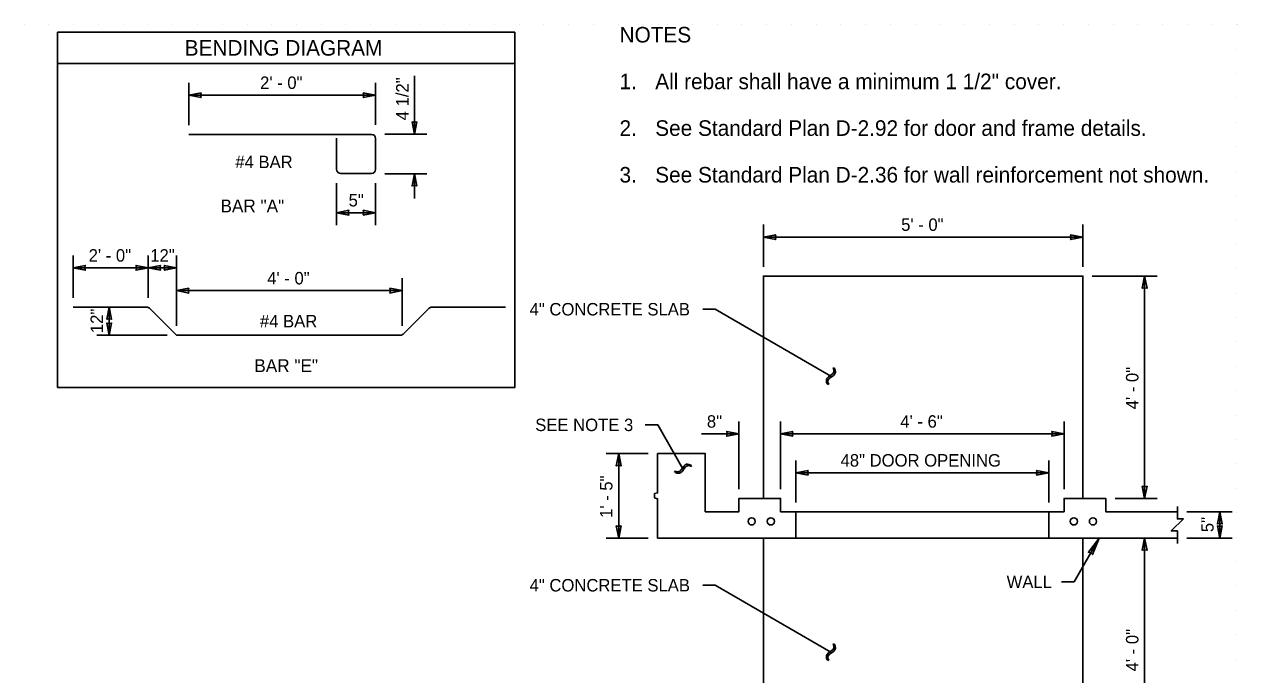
# Model space of a CAD drawing. Extents: x 99862 to 103151, y 100000 to 102076.
# Drawn here: x 101591 to 103151, y 101240 to 102076 of the extents above; entities that cross this region are included whole.
import ezdxf

# ---------------------------------------------------------------- set-up
doc = ezdxf.new("R2010")
doc.units = 0
for name, color, linetype in [('Level 1', 7, 'Continuous'), ('Level 13', 7, 'Continuous'), ('Level 15', 7, 'Continuous'), ('Level 16', 7, 'Continuous'), ('Level 17', 7, 'Continuous'), ('Level 19', 7, 'Continuous'), ('Level 20', 7, 'Continuous'), ('Level 60', 7, 'Continuous')]:
    doc.layers.add(name, color=color, linetype=linetype)

msp = doc.modelspace()

# ---------------------------------------------------------------- linework, layer by layer
at = {"layer": 'Level 1'}
for p, q in [((101590.9, 102075), (101590.9, 102075)), ((101622.7, 102075), (101622.7, 102075)), ((101654.5, 102075), (101654.5, 102075)), ((101686.4, 102075), (101686.4, 102075)), ((101718.2, 102075), (101718.2, 102075)), ((101750, 102075), (101750, 102075)), ((101781.8, 102075), (101781.8, 102075)), ((101813.6, 102075), (101813.6, 102075)), ((101845.5, 102075), (101845.5, 102075)), ((101877.3, 102075), (101877.3, 102075)), ((101909.1, 102075), (101909.1, 102075)), ((101940.9, 102075), (101940.9, 102075)), ((101972.7, 102075), (101972.7, 102075)), ((102004.5, 102075), (102004.5, 102075)), ((102036.4, 102075), (102036.4, 102075)), ((102068.2, 102075), (102068.2, 102075)), ((102100, 102075), (102100, 102075)), ((102131.8, 102075), (102131.8, 102075)), ((102163.6, 102075), (102163.6, 102075)), ((102195.5, 102075), (102195.5, 102075)), ((102227.3, 102075), (102227.3, 102075)), ((102259.1, 102075), (102259.1, 102075)), ((102290.9, 102075), (102290.9, 102075)), ((102322.7, 102075), (102322.7, 102075)), ((102354.5, 102075), (102354.5, 102075)), ((102386.4, 102075), (102386.4, 102075)), ((102418.2, 102075), (102418.2, 102075)), ((102450, 102075), (102450, 102075)), ((102481.8, 102075), (102481.8, 102075)), ((102513.6, 102075), (102513.6, 102075)), ((102545.5, 102075), (102545.5, 102075)), ((102577.3, 102075), (102577.3, 102075)), ((102609.1, 102075), (102609.1, 102075)), ((102640.9, 102075), (102640.9, 102075)), ((102672.7, 102075), (102672.7, 102075)), ((102704.5, 102075), (102704.5, 102075)), ((102736.4, 102075), (102736.4, 102075)), ((102768.2, 102075), (102768.2, 102075)), ((102800, 102075), (102800, 102075)), ((102831.8, 102075), (102831.8, 102075)), ((102863.6, 102075), (102863.6, 102075)), ((102895.5, 102075), (102895.5, 102075)), ((102927.3, 102075), (102927.3, 102075)), ((102959.1, 102075), (102959.1, 102075)), ((102990.9, 102075), (102990.9, 102075)), ((103022.7, 102075), (103022.7, 102075)), ((103054.5, 102075), (103054.5, 102075)), ((103086.4, 102075), (103086.4, 102075)), ((103118.2, 102075), (103118.2, 102075)), ((103150, 102075), (103150, 102075)), ((103150, 102043.6), (103150, 102043.6)), ((103150, 102012.3), (103150, 102012.3)), ((103150, 101980.9), (103150, 101980.9)), ((103150, 101949.6), (103150, 101949.6)), ((103150, 101918.2), (103150, 101918.2)), ((103150, 101886.9), (103150, 101886.9)), ((103150, 101855.5), (103150, 101855.5)), ((103150, 101824.2), (103150, 101824.2)), ((103150, 101792.8), (103150, 101792.8)), ((103150, 101761.4), (103150, 101761.4)), ((103150, 101730.1), (103150, 101730.1)), ((103150, 101698.7), (103150, 101698.7)), ((103150, 101667.4), (103150, 101667.4)), ((103150, 101636), (103150, 101636)), ((103150, 101604.7), (103150, 101604.7)), ((103150, 101573.3), (103150, 101573.3)), ((103150, 101541.9), (103150, 101541.9)), ((103150, 101510.6), (103150, 101510.6)), ((103150, 101479.2), (103150, 101479.2)), ((103150, 101447.9), (103150, 101447.9)), ((103150, 101416.5), (103150, 101416.5)), ((103150, 101385.2), (103150, 101385.2)), ((103150, 101353.8), (103150, 101353.8)), ((103150, 101322.5), (103150, 101322.5)), ((103150, 101291.1), (103150, 101291.1)), ((103150, 101259.7), (103150, 101259.7))]:
    msp.add_line(p, q, dxfattribs=at)
at = {"layer": 'Level 13'}
for p, q in [((101802.5, 101933.9), (102037.5, 101933.9)), ((101992.5, 101888.9), (101992.5, 101929.1)), ((102042.5, 101928.9), (102042.5, 101888.9)), ((102037.5, 101883.9), (101997.5, 101883.9))]:
    msp.add_line(p, q, dxfattribs=at)
for points in [[(101653.7, 101712.1), (101748.3, 101712.1)], [(101751.8, 101710.6), (101785.2, 101677.3)], [(102078.1, 101677.3), (102111.5, 101710.6)], [(102115, 101712.1), (102209.6, 101712.1)], [(101788.7, 101675.8), (102074.6, 101675.8)]]:
    msp.add_lwpolyline(points, dxfattribs=at)
for centre in [(102526.1, 101436.7), (102550.7, 101436.7), (102940.3, 101436.7), (102964.9, 101436.7)]:
    msp.add_circle(centre, 4.63, dxfattribs=at)
for centre, start, end in [((102037.5, 101928.9), 0, 90), ((101997.5, 101888.9), 180, 270), ((102037.5, 101888.9), 270, 0), ((101748.3, 101707.1), 45, 90), ((102115, 101707.1), 90, 135), ((101788.7, 101680.8), 225, 270), ((102074.6, 101680.8), 270, 315)]:
    msp.add_arc(centre, 5, start, end, dxfattribs=at)
at = {"layer": 'Level 15'}
for p, q in [((101802.5, 102000.4), (101802.5, 101945.9)), ((102042.5, 102000.4), (102042.5, 101946.3)), ((102092.5, 102009.2), (102092.5, 101934.3)), ((102042.5, 101984.4), (101802.5, 101984.4)), ((102108.5, 101934.3), (102054.5, 101934.3)), ((102108.5, 101883.4), (102054.5, 101883.4)), ((102092.5, 101883.4), (102092.5, 101851.4)), ((101992.5, 101871.4), (101992.5, 101817.4)), ((102042.5, 101871.4), (102042.5, 101817.4)), ((102042.5, 101833.4), (101992.5, 101833.4)), ((102541.3, 101764), (102541.3, 101818)), ((102951.9, 101764), (102951.9, 101818)), ((102951.9, 101802), (102541.3, 101802)), ((101653.7, 101778.5), (101653.7, 101724.1)), ((101750.4, 101778.5), (101750.4, 101724.1)), ((101786.6, 101778.5), (101786.6, 101687.8)), ((101750.4, 101762.5), (101653.7, 101762.5)), ((101786.6, 101762.5), (101750.4, 101762.5)), ((103047.3, 101752), (102963.9, 101752)), ((103031.3, 101466.1), (103031.3, 101752)), ((102076.7, 101749.2), (102076.7, 101687.8)), ((102076.7, 101733.2), (101786.6, 101733.2)), ((101700.1, 101712.1), (101700.1, 101675.8)), ((102463.2, 101709.3), (102479.2, 101709.3)), ((102628, 101623.4), (102479.2, 101709.3)), ((101774.6, 101675.8), (101684.1, 101675.8)), ((102509.7, 101478.1), (102509.7, 101565.1)), ((102563.3, 101478.1), (102563.3, 101565.1)), ((102927.7, 101478.1), (102927.7, 101565.1)), ((102389.3, 101560.7), (102405.3, 101560.7)), ((102437.8, 101504.4), (102405.3, 101560.7)), ((102461.5, 101549.1), (102509.7, 101549.1)), ((102927.7, 101549.1), (102563.3, 101549.1)), ((102339.1, 101523.7), (102393.1, 101523.7)), ((102355.1, 101415.2), (102355.1, 101523.7)), ((102583, 101461.1), (102583, 101515.1)), ((102908, 101461.1), (102908, 101515.1)), ((102908, 101499.1), (102583, 101499.1)), ((103047.3, 101466.1), (102993.3, 101466.1)), ((103085.4, 101449.1), (103144, 101449.1)), ((103128, 101415.2), (103128, 101449.1)), ((102339.1, 101415.2), (102393.1, 101415.2)), ((102973, 101415.2), (102940.5, 101358.9)), ((103031.3, 101415.2), (103031.3, 101129.3)), ((103085.4, 101415.2), (103144, 101415.2)), ((102463.2, 101354.6), (102479.2, 101354.6)), ((102628, 101268.7), (102479.2, 101354.6)), ((102924.5, 101358.9), (102940.5, 101358.9))]:
    msp.add_line(p, q, dxfattribs=at)
for points in [[(101802.5, 101984.4), (101818.2, 101981.3), (101817.5, 101984.4), (101818.2, 101987.4)], [(102042.5, 101984.4), (102026.8, 101987.4), (102027.5, 101984.4), (102026.8, 101981.3)], [(102092.5, 101934.3), (102095.6, 101950.1), (102092.5, 101949.3), (102089.4, 101950.1)], [(102092.5, 101883.4), (102089.4, 101867.7), (102092.5, 101868.4), (102095.6, 101867.7)], [(101992.5, 101833.4), (102008.2, 101830.3), (102007.5, 101833.4), (102008.2, 101836.5)], [(102042.5, 101833.4), (102026.8, 101836.5), (102027.5, 101833.4), (102026.8, 101830.3)], [(102541.3, 101802), (102557.1, 101805.1), (102556.3, 101802), (102557.1, 101798.9)], [(102951.9, 101802), (102936.2, 101798.9), (102936.9, 101802), (102936.2, 101805.1)], [(101653.7, 101762.5), (101669.4, 101759.4), (101668.7, 101762.5), (101669.4, 101765.6)], [(101750.4, 101762.5), (101734.6, 101765.6), (101735.4, 101762.5), (101734.6, 101759.4)], [(101750.4, 101762.5), (101766.1, 101759.4), (101765.4, 101762.5), (101766.1, 101765.6)], [(101786.6, 101762.5), (101770.9, 101765.6), (101771.6, 101762.5), (101770.9, 101759.4)], [(103031.3, 101752), (103034.4, 101736.3), (103031.3, 101737), (103028.2, 101736.3)], [(101786.6, 101733.2), (101802.3, 101730.1), (101801.6, 101733.2), (101802.3, 101736.2)], [(102076.7, 101733.2), (102060.9, 101736.2), (102061.7, 101733.2), (102060.9, 101730.1)], [(101700.1, 101712.1), (101697.1, 101696.4), (101700.1, 101697.1), (101703.2, 101696.4)], [(101700.1, 101675.8), (101703.2, 101691.6), (101700.1, 101690.8), (101697.1, 101691.6)], [(102509.7, 101549.1), (102494, 101552.2), (102494.7, 101549.1), (102494, 101546.1)], [(102563.3, 101549.1), (102579, 101552.2), (102578.3, 101549.1), (102579, 101546.1)], [(102927.7, 101549.1), (102912, 101546.1), (102912.7, 101549.1), (102912, 101552.2)], [(102355.1, 101523.7), (102352, 101507.9), (102355.1, 101508.7), (102358.2, 101507.9)], [(102583, 101499.1), (102598.7, 101502.2), (102598, 101499.1), (102598.7, 101496.1)], [(102908, 101499.1), (102892.3, 101496.1), (102893, 101499.1), (102892.3, 101502.2)], [(103031.3, 101466.1), (103028.2, 101481.8), (103031.3, 101481.1), (103034.4, 101481.8)], [(103128, 101449.1), (103124.9, 101433.4), (103128, 101434.1), (103131.1, 101433.4)], [(102355.1, 101415.2), (102352, 101430.9), (102355.1, 101430.2), (102358.2, 101430.9)], [(103128, 101415.2), (103124.9, 101430.9), (103128, 101430.2), (103131.1, 101430.9)], [(102973, 101415.2), (102964.2, 101393.9), (102962.1, 101396.3), (102959, 101396.9)], [(103031.3, 101415.2), (103028.2, 101399.5), (103031.3, 101400.2), (103034.4, 101399.5)]]:
    msp.add_lwpolyline(points, close=True, dxfattribs=at)
msp.add_lwpolyline([(103073.4, 101455.9), (103073.4, 101439.9), (103081.1, 101439.9), (103065.6, 101424.4), (103073.4, 101424.4), (103073.4, 101408.4)], dxfattribs=at)
at = {"layer": 'Level 16'}
for points in [[(102466.4, 101449.1), (102509.7, 101449.1), (102509.7, 101466.1), (102563.3, 101466.1), (102563.3, 101449.1), (102583, 101449.1), (102583, 101415.2), (102405.1, 101415.2), (102405.1, 101465.8), (102401.2, 101466.8), (102401.2, 101472.4), (102405.1, 101473.3), (102405.1, 101523.7), (102466.4, 101523.7)], [(102981.3, 101449.1), (103073.4, 101449.1), (103073.4, 101439.9), (103081.1, 101439.9), (103065.6, 101424.4), (103073.4, 101424.4), (103073.4, 101415.2), (102908, 101415.2), (102908, 101449.1), (102927.7, 101449.1), (102927.7, 101466.1), (102981.3, 101466.1)]]:
    msp.add_lwpolyline(points, close=True, dxfattribs=at)
at = {"layer": 'Level 17'}
for points in [[(102541.3, 101466.1), (102541.3, 101752), (102951.9, 101752), (102951.9, 101466.1)], [(102405.1, 101415.2), (102405.1, 101465.8), (102401.2, 101466.8), (102401.2, 101472.4), (102405.1, 101473.3), (102405.1, 101523.7), (102466.4, 101523.7), (102466.4, 101449.1), (102509.7, 101449.1), (102509.7, 101466.1), (102563.3, 101466.1), (102563.3, 101449.1), (102583, 101449.1), (102583, 101415.2), (102405.1, 101415.2)], [(103073.4, 101449.1), (102981.3, 101449.1), (102981.3, 101466.1), (102927.7, 101466.1), (102927.7, 101449.1), (102908, 101449.1), (102908, 101415.2), (103073.4, 101415.2)], [(102583, 101449.1), (102908, 101449.1)], [(102541.3, 101415.2), (102541.3, 101129.3), (102951.9, 101129.3), (102951.9, 101415.2)], [(102583, 101415.2), (102908, 101415.2)]]:
    msp.add_lwpolyline(points, dxfattribs=at)
at = {"layer": 'Level 19'}
for points in [[(102221.7, 102065.3), (101633.8, 102065.3), (101633.8, 102025.1), (102221.7, 102025.1)], [(102221.7, 102025.1), (101633.8, 102025.1), (101633.8, 101608.9), (102221.7, 101608.9)]]:
    msp.add_lwpolyline(points, close=True, dxfattribs=at)
at = {"layer": 'Level 20'}
for p, q in [((102624.8, 101622.6), (102628.5, 101625.1)), ((102628.5, 101625.1), (102630.4, 101626.5)), ((102630.4, 101626.5), (102631.4, 101627.6)), ((102631.9, 101630.6), (102631, 101634.2)), ((102631, 101634.2), (102632.8, 101633.2)), ((102631.4, 101627.6), (102631.9, 101629)), ((102633, 101626.2), (102631.5, 101624.3)), ((102631.9, 101629), (102631.9, 101630.6)), ((102632.8, 101633.2), (102633.6, 101631.1)), ((102633.7, 101627.8), (102633, 101626.2)), ((102633.6, 101631.1), (102633.8, 101629.4)), ((102633.8, 101629.4), (102633.7, 101627.8)), ((102622.2, 101617.2), (102622.4, 101618.9)), ((102622.5, 101615.4), (102622.2, 101617.2)), ((102622.4, 101618.9), (102623.1, 101620.5)), ((102623.3, 101613.6), (102622.5, 101615.4)), ((102623.1, 101620.5), (102624.8, 101622.6)), ((102625.1, 101612.5), (102623.3, 101613.6)), ((102624.2, 101617.9), (102624.1, 101616.5)), ((102624.1, 101616.5), (102624.4, 101614.8)), ((102624.7, 101619.1), (102624.2, 101617.9)), ((102624.4, 101614.8), (102625.1, 101612.5)), ((102626, 101620.6), (102624.7, 101619.1)), ((102628.1, 101622.1), (102626, 101620.6)), ((102631.5, 101624.3), (102628.1, 101622.1)), ((102429.3, 101500.7), (102427, 101501.4)), ((102427, 101501.4), (102428, 101499.6)), ((102428, 101499.6), (102429.8, 101498.8)), ((102431, 101500.4), (102429.3, 101500.7)), ((102432.3, 101500.6), (102431, 101500.4)), ((102433.6, 101501.1), (102432.3, 101500.6)), ((102435, 101502.3), (102433.6, 101501.1)), ((102434.9, 101499.4), (102437, 101501.2)), ((102436.5, 101504.4), (102435, 101502.3)), ((102438.8, 101507.8), (102436.5, 101504.4)), ((102437, 101501.2), (102439.5, 101504.8)), ((102440.7, 101509.4), (102438.8, 101507.8)), ((102439.5, 101504.8), (102440.9, 101506.8)), ((102442.2, 101510), (102440.7, 101509.4)), ((102440.9, 101506.8), (102442.1, 101507.7)), ((102442.1, 101507.7), (102443.4, 101508.2)), ((102443.8, 101510.2), (102442.2, 101510)), ((102443.4, 101508.2), (102445.1, 101508.3)), ((102445.6, 101509.9), (102443.8, 101510.2)), ((102445.1, 101508.3), (102448.6, 101507.3)), ((102447.6, 101509.2), (102445.6, 101509.9)), ((102448.6, 101507.3), (102447.6, 101509.2)), ((102429.8, 101498.8), (102431.6, 101498.6)), ((102431.6, 101498.6), (102433.3, 101498.8)), ((102433.3, 101498.8), (102434.9, 101499.4)), ((102622.4, 101264.2), (102623.1, 101265.8)), ((102623.1, 101265.8), (102624.8, 101267.9)), ((102626, 101265.9), (102624.7, 101264.4)), ((102624.8, 101267.9), (102628.5, 101270.4)), ((102628.1, 101267.3), (102626, 101265.9)), ((102631.5, 101269.6), (102628.1, 101267.3)), ((102628.5, 101270.4), (102630.4, 101271.8)), ((102630.4, 101271.8), (102631.4, 101272.9)), ((102631.9, 101275.9), (102631, 101279.5)), ((102631, 101279.5), (102632.8, 101278.4)), ((102631.4, 101272.9), (102631.9, 101274.3)), ((102633, 101271.5), (102631.5, 101269.6)), ((102631.9, 101274.3), (102631.9, 101275.9)), ((102632.8, 101278.4), (102633.6, 101276.4)), ((102633.7, 101273.1), (102633, 101271.5)), ((102633.6, 101276.4), (102633.8, 101274.7)), ((102633.8, 101274.7), (102633.7, 101273.1)), ((102622.2, 101262.5), (102622.4, 101264.2)), ((102622.5, 101260.7), (102622.2, 101262.5)), ((102623.3, 101258.9), (102622.5, 101260.7)), ((102625.1, 101257.8), (102623.3, 101258.9)), ((102624.2, 101263.2), (102624.1, 101261.8)), ((102624.1, 101261.8), (102624.4, 101260.1)), ((102624.7, 101264.4), (102624.2, 101263.2)), ((102624.4, 101260.1), (102625.1, 101257.8))]:
    msp.add_line(p, q, dxfattribs=at)
at = {"layer": 'Level 60'}
msp.add_line((103151, 102075.5), (103151, 102075.5), dxfattribs=at)

# ---------------------------------------------------------------- texts
at = {"layer": 'Level 19'}
msp.add_text('BENDING DIAGRAM', height=20, dxfattribs=at).set_placement((101797.2, 102035.2))
at = {"layer": 'Level 20'}
for s, height, p in [('NOTES', 20, (102356.2, 102052.1)), ('2\' - 0"', 16, (101894.1, 101992.4)), ('1.', 20, (102356.2, 101992.1)), ('All rebar shall have a minimum 1 1/2" cover.', 20, (102402.1, 101992.1)), ('2.', 20, (102356.2, 101932.1)), ('See Standard Plan D-2.92 for door and frame details.', 20, (102402.1, 101932.1)), ('#4 BAR', 16, (101862.3, 101890.6)), ('3.', 20, (102356.2, 101872.1)), ('See Standard Plan D-2.36 for wall reinforcement not shown.', 20, (102402.1, 101872.1)), ('BAR "A"', 16.5, (101843.2, 101833.8)), ('5"', 16, (102007.9, 101841.4)), ('2\' - 0"', 16, (101673.7, 101770.5)), ('12"', 16, (101752.9, 101770.5)), ('4\' - 0"', 16, (101903.3, 101741.2)), ('4" CONCRETE SLAB', 16, (102240.6, 101701.3)), ('#4 BAR', 16, (101893.9, 101686)), ('BAR "E"', 16.5, (101886.7, 101628.5)), ('SEE NOTE 3', 16, (102247.8, 101552.7)), ('4" CONCRETE SLAB', 16, (102240.6, 101346.6))]:
    msp.add_text(s, height=height, dxfattribs=at).set_placement(p)
for s, rotation, p in [('4 1/2"', 90, (102085, 101952.1)), ('5\' - 0"', 360, (102718.3, 101810)), ('12"', 90, (101692.1, 101678.6)), ('4\' - 0"', 90, (103023.3, 101580.7)), ('8"', 360, (102468.5, 101557.1)), ('4\' - 6"', 360, (102717.2, 101557.1)), ('48" DOOR OPENING', 360, (102640.4, 101507.1)), ('1\' - 5"', 90, (102347.1, 101441.1)), ('5"', 90, (103120, 101422.8)), ('WALL', 360, (102853.9, 101350.9)), ('4\' - 0"', 90, (103023.3, 101243.9))]:
    msp.add_text(s, height=16, rotation=rotation, dxfattribs=at).set_placement(p)

doc.saveas('drawing.dxf')
